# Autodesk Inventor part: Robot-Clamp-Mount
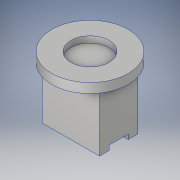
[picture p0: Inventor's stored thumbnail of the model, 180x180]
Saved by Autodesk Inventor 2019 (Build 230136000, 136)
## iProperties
Created: 2018-07
Part Number: Robot-Clamp-Mount
Material: Aluminum 6061
Description: 123456
Document SubType Name: Modeling
Designer: Power User
Mass: 486.263 g
Surface Area: 257.832 cm^2
Volume: 180.097 cm^3
Density: 2.7 g/cm^3
Appearance: Aluminum - Flat
Title: GEAR
Author: Power User
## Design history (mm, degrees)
sketch "Sketch6"
  geometry: L1 (60, 20)-(0, 20); L2 (0, -20)-(60, -20); L3 (60, -20)-(60, 20); L4 (0, 10)-(5, 10); L5 (5, 10)-(5, -10); L6 (5, -10)-(0, -10); L7 (0, 20)-(0, 10); L8 (0, -10)-(0, -20); 4 further points
  constraints: 16 end point, 7 perpendicular, 3 parallel, 2 coincident, 2 horizontal alignment, 2 midpoint, 2 vertical alignment, 1 horizontal
  dimensions: "d44" = 40 distance between parallel lines of L2 L1; "d45" = 20 distance of L4.end L5.end; "d46" = 5 distance from line of L5 point (0, 0); "d47" = 60 distance from line of point (0, 0) L3
extrude "Extrusion5" new body sketch "Sketch6" stored distance "d48" = 60; taper "d49" = 0 deg
sketch "Sketch7"
  geometry: C1 r 40 at (30, 20); 1 further point
  constraints: 1 centre point, 1 coincident
  dimensions: "d50" = 80 diameter of C1
extrude "Extrusion6" join sketch "Sketch7" distance "d51" = 10; taper "d52" = 0 deg
sketch "Sketch8"
  geometry: C1 r 40 at (0, 0) reference; 2 further points
  constraints: 1 coincident
hole "Hole2" sketch "Sketch8" at (0, 0) diameter "d53" = 40; stored, may be unused: countersink angle "d57" = 90 deg, drill point angle "d59" = 0 deg; dims "d54" = 6, "d55" = 4, "d56" = 2, "d58" = 6.5
body "Solid2"
